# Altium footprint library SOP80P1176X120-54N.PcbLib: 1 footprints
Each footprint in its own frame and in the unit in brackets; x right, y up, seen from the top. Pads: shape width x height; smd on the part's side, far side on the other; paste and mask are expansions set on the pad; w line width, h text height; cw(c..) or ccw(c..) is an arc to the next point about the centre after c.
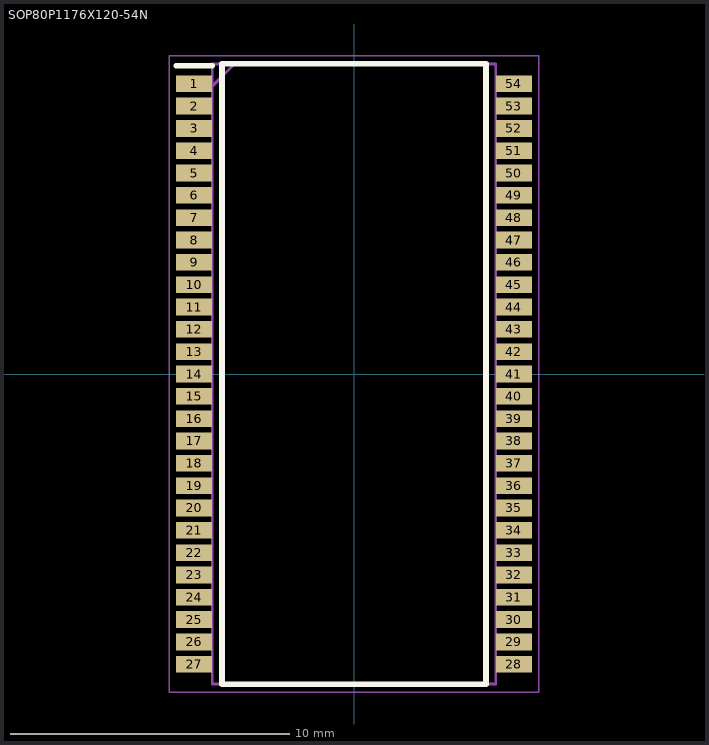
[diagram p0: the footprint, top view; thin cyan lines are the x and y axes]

## SOP80P1176X120-54N [mm]
pads (54):
  rect 1.295x0.6 smd: 1(-5.728,10.4) 2(-5.728,9.6) 3(-5.728,8.8) 4(-5.728,8) 5(-5.728,7.2) 6(-5.728,6.4) 7(-5.728,5.6) 8(-5.728,4.8) 9(-5.728,4) 10(-5.728,3.2) 11(-5.728,2.4) 12(-5.728,1.6) 13(-5.728,0.8) 14(-5.728,0) 15(-5.728,-0.8) 16(-5.728,-1.6) 17(-5.728,-2.4) 18(-5.728,-3.2) 19(-5.728,-4) 20(-5.728,-4.8) 21(-5.728,-5.6) 22(-5.728,-6.4) 23(-5.728,-7.2) 24(-5.728,-8) 25(-5.728,-8.8) 26(-5.728,-9.6) 27(-5.728,-10.4) 28(5.728,-10.4) 29(5.728,-9.6) 30(5.728,-8.8) 31(5.728,-8) 32(5.728,-7.2) 33(5.728,-6.4) 34(5.728,-5.6) 35(5.728,-4.8) 36(5.728,-4) 37(5.728,-3.2) 38(5.728,-2.4) 39(5.728,-1.6) 40(5.728,-0.8) 41(5.728,0) 42(5.728,0.8) 43(5.728,1.6) 44(5.728,2.4) 45(5.728,3.2) 46(5.728,4) 47(5.728,4.8) 48(5.728,5.6) 49(5.728,6.4) 50(5.728,7.2) 51(5.728,8) 52(5.728,8.8) 53(5.728,9.6) 54(5.728,10.4)
Top Overlay:
  lines w0.2: -6.375,11.05 -5.08,11.05 ; -4.73,-11.11 4.73,-11.11 4.73,11.11 -4.73,11.11 -4.73,-11.11
Mechanical 15:
  lines w0.1: -5.08,10.31 -4.28,11.11 ; -5.08,-11.11 5.08,-11.11 5.08,11.11 -5.08,11.11 -5.08,-11.11
Mechanical 20:
  lines w0.05: -6.625,-11.4 6.625,-11.4 6.625,11.4 -6.625,11.4 -6.625,-11.4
